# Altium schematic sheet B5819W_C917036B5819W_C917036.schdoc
size 127 x 101 mm
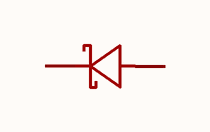
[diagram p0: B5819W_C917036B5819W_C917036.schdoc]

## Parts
D?  b5819w_c917036  [SOD-123_L2.8-W1.8-LS3.7-RD-1]  (value not drawn)

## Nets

Not connected (* = marked no-connect by the designer): D? 1(K) 2(A)

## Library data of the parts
D? = b5819w_c917036: 二极管配置:独立式;正向压降(Vf):900mV@3A;直流反向耐压(Vr):40V;整流电流:1A;; Manufacturer: JSMSEMI(杰盛微); ManufacturerPart: B5819W; AddInBom: yes; ModelId: 6dee1caa2d304f1db7861ac827c1b985; ModelTransform: 144.964,64.961,0,0,0,0,0,0,0; Diode Configuration: 独立式; Voltage - DC Reverse(Vr): 40V; Current - Rectified: 1A; Reverse Leakage Current (Ir): 1mA@40V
